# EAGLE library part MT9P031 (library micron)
MT9P031: 1/2.5-Inch 5-Mp CMOS Image Sensor Source: http://download.micron.com/pdf/product_brief/MT9P031_5100_PB.pdf
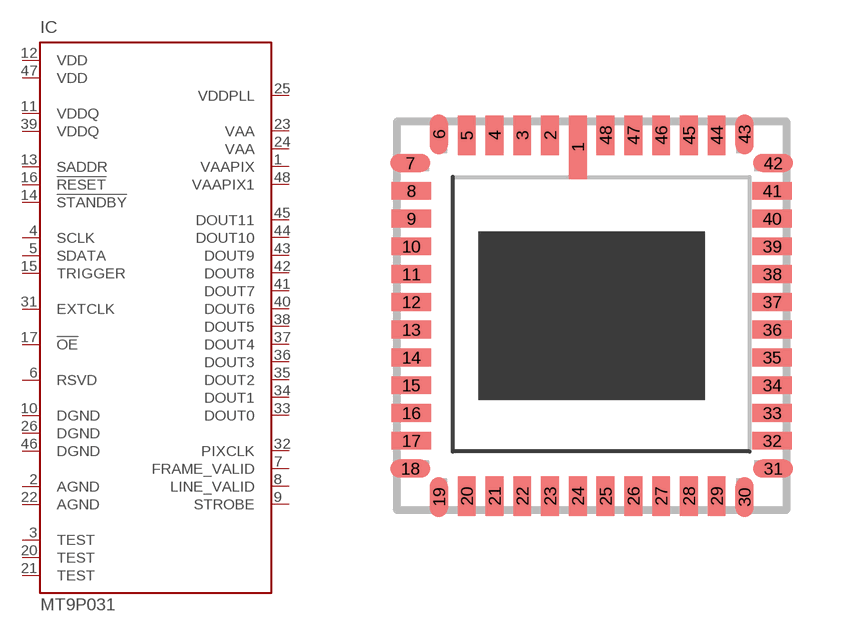
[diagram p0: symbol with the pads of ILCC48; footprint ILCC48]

Designator prefix IC

## MT9P031 (MPN: MT9P031I12STM; OC_FARNELL: 1695390; OC_NEWARK: 80P6535)  [ILCC48]
1  VAAPIX  pwr
2  AGND  pwr
3  TEST  in
4  SCLK  in
5  SDATA  in
6  RSVD  in
7  FRAME_VALID  out
8  LINE_VALID  out
9  STROBE  out
10  DGND  pwr
11  VDDQ  pwr
12  VDD  pwr
13  SADDR  in
14  !STANDBY  in
15  TRIGGER  in
16  !RESET  in
17  !OE  in
20  TEST  in
21  TEST  in
22  AGND  pwr
23  VAA  pwr
24  VAA  pwr
25  VDDPLL  pwr
26  DGND  pwr
31  EXTCLK  in
32  PIXCLK  out
33  DOUT0  out
34  DOUT1  out
35  DOUT2  out
36  DOUT3  out
37  DOUT4  out
38  DOUT5  out
39  VDDQ  pwr
40  DOUT6  out
41  DOUT7  out
42  DOUT8  out
43  DOUT9  out
44  DOUT10  out
45  DOUT11  out
46  DGND  pwr
47  VDD  pwr
48  VAAPIX1  pwr

## Footprint ILCC48 (pad centres in mm)
48-Pin iLCC Package MT9P031: 1/2.5-Inch 5-Mp Digital Image Sensor Source: http://download.micron.com/pdf/product_brief/MT9P031_5100_PB.pdf
smd 0.45 x 1.6: 1 -0.35,4.25
smd 0.45 x 1: 2 -1.05,4.55; 3 -1.75,4.55; 4 -2.45,4.55; 5 -3.15,4.55; 6 -3.85,4.575; 19 -3.85,-4.575; 20 -3.15,-4.55; 21 -2.45,-4.55; 22 -1.75,-4.55; 23 -1.05,-4.55; 24 -0.35,-4.55; 25 0.35,-4.55; 26 1.05,-4.55; 27 1.75,-4.55; 28 2.45,-4.55; 29 3.15,-4.55; 30 3.85,-4.575; 43 3.85,4.575; 44 3.15,4.55; 45 2.45,4.55; 46 1.75,4.55; 47 1.05,4.55; 48 0.35,4.55
smd 1 x 0.45: 7 -4.575,3.85; 8 -4.55,3.15; 9 -4.55,2.45; 10 -4.55,1.75; 11 -4.55,1.05; 12 -4.55,0.35; 13 -4.55,-0.35; 14 -4.55,-1.05; 15 -4.55,-1.75; 16 -4.55,-2.45; 17 -4.55,-3.15; 18 -4.575,-3.85; 31 4.575,-3.85; 32 4.55,-3.15; 33 4.55,-2.45; 34 4.55,-1.75; 35 4.55,-1.05; 36 4.55,-0.35; 37 4.55,0.35; 38 4.55,1.05; 39 4.55,1.75; 40 4.55,2.45; 41 4.55,3.15; 42 4.575,3.85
